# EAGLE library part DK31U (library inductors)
FILTER
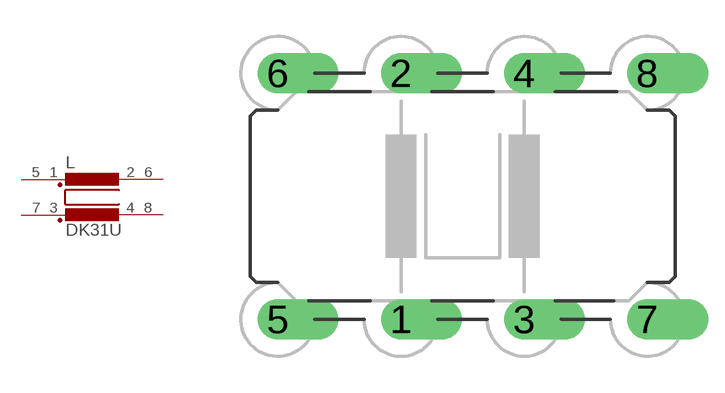
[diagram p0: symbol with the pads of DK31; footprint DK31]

Designator prefix L

## DK31U  [DK31]
1  1  pas
2  2  pas
3  3  pas
4  4  pas
5  5  pas
6  6  pas
7  7  pas
8  8  pas

## Footprint DK31 (pad centres in mm)
FILTER manufacturer Vogt
drill 1.118 offset: 1 -2.54,-5.08; 2 -2.54,5.08; 3 2.54,-5.08; 4 2.54,5.08; 5 -7.62,-5.08; 6 -7.62,5.08; 7 7.62,-5.08; 8 7.62,5.08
